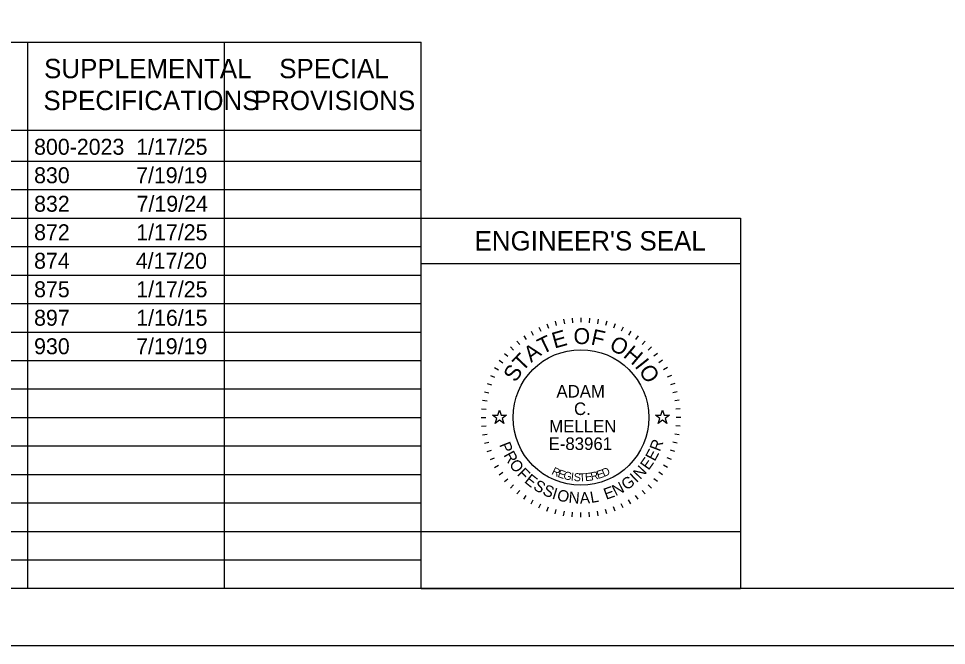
# Model space of a CAD drawing. Extents: x 0 to 170000, y 0 to 110000.
# Drawn here: x 100344 to 141026, y 0 to 27500 of the extents above; entities that cross this region are included whole.
import ezdxf

# ---------------------------------------------------------------- set-up
doc = ezdxf.new("R2010")
doc.units = 0
for name, color, linetype in [('Default', 7, 'Continuous'), ('SH_Border', 7, 'Continuous'), ('SH_Cut_Line', 7, 'Continuous'), ('SH_Data', 7, 'Continuous'), ('SH_Text', 7, 'Continuous')]:
    doc.layers.add(name, color=color, linetype=linetype)

msp = doc.modelspace()

# ---------------------------------------------------------------- linework, layer by layer
at = {"layer": 'Default'}
for points in [[(121118, 10100), (121353, 10100), (121425, 10323), (121497, 10100), (121732, 10100), (121542, 9962), (121615, 9739), (121425, 9877), (121235, 9739), (121308, 9962)], [(128268, 10100), (128503, 10100), (128575, 10323), (128647, 10100), (128882, 10100), (128692, 9962), (128765, 9739), (128575, 9877), (128385, 9739), (128458, 9962)]]:
    msp.add_lwpolyline(points, close=True, dxfattribs=at)
at = {"layer": 'SH_Border'}
msp.add_lwpolyline([(7500, 107500), (167500, 107500), (167500, 2500), (7500, 2500)], close=True, dxfattribs=at)
at = {"layer": 'SH_Cut_Line'}
msp.add_lwpolyline([(0, 0), (170000, 0), (170000, 110000), (0, 110000)], close=True, dxfattribs=at)
at = {"layer": 'SH_Data'}
for p, q in [((50750, 26459), (118000, 26459)), ((100750, 2500), (100750, 26459)), ((109375, 2500), (109375, 26459)), ((118000, 2500), (118000, 26459)), ((50750, 22605), (118000, 22605)), ((50750, 21250), (118000, 21250)), ((50750, 20000), (118000, 20000)), ((50750, 18750), (118000, 18750)), ((118000, 2500), (118000, 18750)), ((118000, 18750), (132000, 18750)), ((132000, 18750), (132000, 2500)), ((50750, 17500), (118000, 17500)), ((118000, 16750), (132000, 16750)), ((50750, 16250), (118000, 16250)), ((50750, 15000), (118000, 15000)), ((124240, 14309), (124275, 14112)), ((124619, 14358), (124636, 14159)), ((125000, 14375), (125000, 14175)), ((125381, 14358), (125364, 14159)), ((125760, 14309), (125725, 14112)), ((123151, 13965), (123236, 13784)), ((123504, 14111), (123572, 13923)), ((123868, 14226), (123919, 14033)), ((126132, 14226), (126081, 14033)), ((126496, 14111), (126428, 13923)), ((126849, 13965), (126764, 13784)), ((50750, 13750), (118000, 13750)), ((122491, 13584), (122605, 13420)), ((122813, 13789), (122913, 13616)), ((127187, 13789), (127087, 13616)), ((127509, 13584), (127395, 13420)), ((121906, 13094), (122048, 12952)), ((122188, 13351), (122316, 13198)), ((127812, 13351), (127684, 13198)), ((128094, 13094), (127952, 12952)), ((121649, 12812), (121802, 12684)), ((128351, 12812), (128198, 12684)), ((50750, 12500), (118000, 12500)), ((121416, 12509), (121580, 12395)), ((128584, 12509), (128420, 12395)), ((121035, 11849), (121216, 11764)), ((121211, 12187), (121384, 12088)), ((128789, 12187), (128616, 12088)), ((128965, 11849), (128784, 11764)), ((120889, 11496), (121077, 11428)), ((129111, 11496), (128923, 11428)), ((50750, 11250), (118000, 11250)), ((120774, 11132), (120967, 11081)), ((129226, 11132), (129033, 11081)), ((120691, 10760), (120888, 10725)), ((129309, 10760), (129112, 10725)), ((120642, 10381), (120841, 10364)), ((129358, 10381), (129159, 10364)), ((50750, 10000), (118000, 10000)), ((120625, 10000), (120825, 10000)), ((129375, 10000), (129175, 10000)), ((120642, 9619), (120841, 9636)), ((129358, 9619), (129159, 9636)), ((120691, 9240), (120888, 9275)), ((129309, 9240), (129112, 9275)), ((50750, 8750), (118000, 8750)), ((120774, 8868), (120967, 8919)), ((120889, 8504), (121077, 8572)), ((129111, 8504), (128923, 8572)), ((129226, 8868), (129033, 8919)), ((121035, 8151), (121216, 8236)), ((128965, 8151), (128784, 8236)), ((121211, 7813), (121384, 7913)), ((128789, 7813), (128616, 7913)), ((50750, 7500), (118000, 7500)), ((121416, 7491), (121580, 7605)), ((128584, 7491), (128420, 7605)), ((121649, 7188), (121802, 7316)), ((121906, 6906), (122048, 7048)), ((128094, 6906), (127952, 7048)), ((128351, 7188), (128198, 7316)), ((122188, 6649), (122316, 6802)), ((122491, 6416), (122605, 6580)), ((127509, 6416), (127395, 6580)), ((127812, 6649), (127684, 6802)), ((50750, 6250), (118000, 6250)), ((122813, 6211), (122913, 6384)), ((123151, 6035), (123236, 6216)), ((126849, 6035), (126764, 6216)), ((127187, 6211), (127087, 6384)), ((123504, 5889), (123572, 6077)), ((123868, 5774), (123919, 5967)), ((124240, 5691), (124275, 5888)), ((124619, 5642), (124636, 5841)), ((125000, 5625), (125000, 5825)), ((125381, 5642), (125364, 5841)), ((125760, 5691), (125725, 5888)), ((126132, 5774), (126081, 5967)), ((126496, 5889), (126428, 6077)), ((50750, 5000), (118000, 5000)), ((50750, 3750), (118000, 3750)), ((118000, 2500), (132000, 2500))]:
    msp.add_line(p, q, dxfattribs=at)
msp.add_lwpolyline([(118000, 2500), (118000, 5000), (132000, 5000), (132000, 2500)], close=True, dxfattribs=at)
msp.add_circle((125000, 10000), 2975, dxfattribs=at)

# ---------------------------------------------------------------- texts
for s, height, p in [("ENGINEER'S SEAL", 850, (120338, 17325)), ('ADAM', 550, (123927, 10875)), ('C.', 550, (124697, 10108)), ('MELLEN', 550, (123611, 9342)), ('E-83961', 550, (123583, 8575))]:
    msp.add_text(s, height=height, dxfattribs=at).set_placement(p)
for s, height, rotation, p in [('E', 700, 15.7571, (123842, 13019)), ('O', 700, 359.7812, (124674, 13221)), ('F', 700, 347.4362, (125405, 13209)), ('T', 700, 25.7167, (123308, 12759)), ('O', 700, 332.2586, (126199, 13008)), ('A', 700, 36.4747, (122817, 12391)), ('H', 700, 319.9136, (126816, 12680)), ('T', 700, 46.4344, (122441, 11982)), ('S', 700, 57.1924, (122140, 11507)), ('I', 700, 308.367, (127332, 12242)), ('O', 700, 303.1491, (127511, 12044)), ('R', 500, 69.2322, (128460, 8477)), ('P', 500, 291.494, (121411, 8810)), ('R', 500, 298.7311, (121595, 8358)), ('E', 500, 61.9951, (128238, 8049)), ('O', 500, 306.4666, (121827, 7941)), ('E', 500, 54.758, (127967, 7657)), ('F', 500, 314.7068, (122171, 7491)), ('R', 350, 334.487, (123687, 7525)), ('D', 350, 23.3052, (126005, 7385)), ('N', 500, 47.0224, (127601, 7254)), ('E', 500, 321.4393, (122489, 7174)), ('E', 350, 341.04, (123953, 7400)), ('G', 350, 347.4752, (124207, 7309)), ('I', 350, 353.7858, (124545, 7234)), ('S', 350, 356.8926, (124679, 7214)), ('T', 350, 3.0061, (124928, 7193)), ('E', 350, 6.0117, (125195, 7206)), ('R', 350, 11.9184, (125462, 7237)), ('E', 350, 17.6836, (125749, 7301)), ('G', 500, 35.0469, (126990, 6785)), ('I', 500, 43.287, (127434, 7107)), ('S', 500, 328.6764, (122872, 6876)), ('S', 500, 335.9134, (123282, 6633)), ('E', 500, 20.0742, (126106, 6385)), ('N', 500, 27.3113, (126522, 6538)), ('I', 500, 343.1505, (123703, 6448)), ('O', 500, 346.8859, (123919, 6376)), ('N', 500, 355.1261, (124444, 6259)), ('A', 500, 2.8617, (124961, 6218)), ('L', 500, 10.0987, (125447, 6245))]:
    msp.add_text(s, height=height, rotation=rotation, dxfattribs=at).set_placement(p)
at = {"layer": 'SH_Text'}
for s, height, p in [('SUPPLEMENTAL', 850, (101463, 24882)), ('SPECIAL', 850, (111771, 24882)), ('SPECIFICATIONS', 850, (101435, 23482)), ('PROVISIONS', 850, (110661, 23482)), ('800-2023', 700, (101025, 21525)), ('1/17/25', 700, (105504, 21525)), ('830', 700, (101025, 20275)), ('7/19/19', 700, (105497, 20275)), ('832', 700, (101025, 19025)), ('7/19/24', 700, (105521, 19025)), ('872', 700, (101025, 17775)), ('1/17/25', 700, (105504, 17775)), ('874', 700, (101025, 16525)), ('4/17/20', 700, (105483, 16525)), ('875', 700, (101025, 15275)), ('1/17/25', 700, (105504, 15275)), ('897', 700, (101025, 14025)), ('1/16/15', 700, (105504, 14025)), ('930', 700, (101025, 12775)), ('7/19/19', 700, (105497, 12775))]:
    msp.add_text(s, height=height, dxfattribs=at).set_placement(p)

doc.saveas('drawing.dxf')
